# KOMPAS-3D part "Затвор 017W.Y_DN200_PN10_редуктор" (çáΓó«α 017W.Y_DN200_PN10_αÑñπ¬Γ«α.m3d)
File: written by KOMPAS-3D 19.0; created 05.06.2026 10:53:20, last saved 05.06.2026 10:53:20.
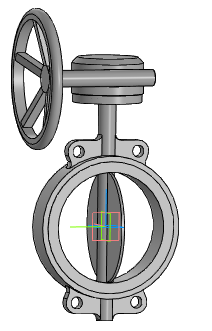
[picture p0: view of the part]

Document properties: Автор: Энергия; Полное имя файла: ..\..\..\3d для проектировщиков\x.x Тип 017W.Y(S) Затвор дисковый поворотный межфланцевый\Затвор 017W.Y(S)_DN50-DN1200_редуктор\Затвор 017W.Y_DN200_PN10_редуктор.a3d

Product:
- Part/product: Затвор 017W.Y_DN200_PN10_редуктор
    Масса: 25.9154

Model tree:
1. Операция без истории:1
